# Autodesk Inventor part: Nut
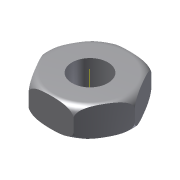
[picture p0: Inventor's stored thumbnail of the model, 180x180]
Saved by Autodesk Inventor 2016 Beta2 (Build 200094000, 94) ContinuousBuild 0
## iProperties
Created: 2009-04
Part Number: Nut
Document SubType Name: Modeling
Designer: Sham
Density: 1 g/cm^3
Material: Generic
Appearance: Default
Author: Sham
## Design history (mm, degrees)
sketch "Sketch1"
  geometry: L1 (7.5, 12.99)-(15, 0); L2 (15, 0)-(7.5, -12.99); L3 (7.5, -12.99)-(-7.5, -12.99); L4 (-7.5, -12.99)-(-15, 0); L5 (-15, 0)-(-7.5, 12.99); L6 (-7.5, 12.99)-(7.5, 12.99); C1 r 6 at (0, 0); 1 further point
  constraints: 12 end point, 1 centre point, 1 coincident, 13 other
  dimensions: "d0" = 30 distance of L1.end L4.end; "d1" = 12 diameter of C1
extrude "Extrusion1" new body sketch "Sketch1" distance "d2" = 12; taper "d3" = 0 deg
sketch "Sketch2"
  geometry: L1 (-12, 0)-(-12, -0.022); L2 (-15, 7)-(-15, 3); L3 (0, -2.87)-(0, 12.87) reference; A1 r 3 centre (-12, 7) between (-12, 10) and (-15, 7); A2 r 3 centre (-12, 3) between (-15, 3) and (-12, 0)
  constraints: 4 end point, 4 point on circle, 2 centre point, 1 tangent
revolve "Revolution1" sketch "Sketch2" stored, may be unused: angle "d7" = 90 deg
body "Solid1"
other parameters: "d6" = 90 deg
